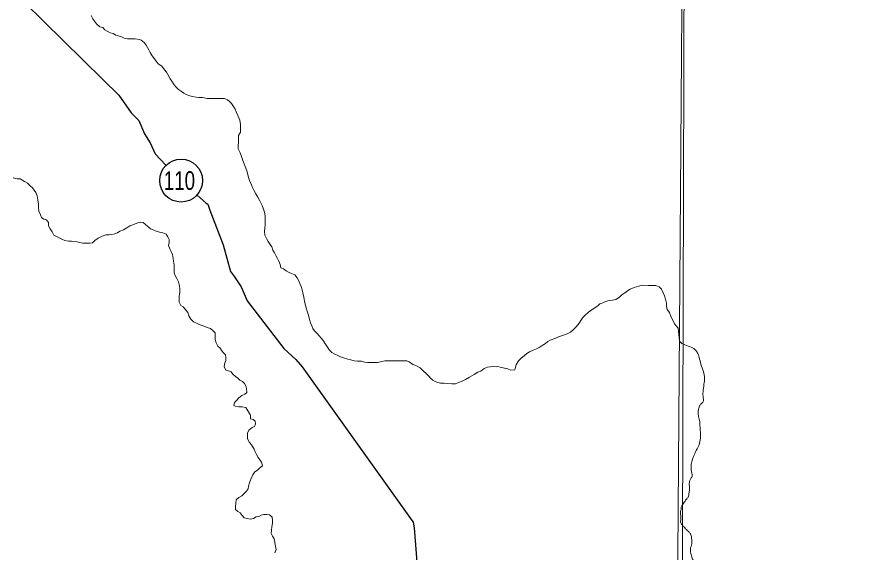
# Model space of a CAD drawing. Extents: x 553962 to 842807, y 8883888 to 9032388.
# Drawn here: x 616016 to 619158, y 8900970 to 8902976 of the extents above; entities that cross this region are included whole.
import ezdxf
from ezdxf.enums import TextEntityAlignment as Align

# ---------------------------------------------------------------- set-up
doc = ezdxf.new("R2010")
doc.units = 0
doc.header["$LTSCALE"] = 20
doc.layers.add('6', color=7, linetype='Continuous', lineweight=13)

msp = doc.modelspace()

# ---------------------------------------------------------------- linework, layer by layer
at = {"layer": '6'}
for points in [[(618662.98, 8924716.12), (618558.35, 8909803.66), (618456.51, 8896026.67)], [(616295.09, 8902981.38), (616301.11, 8902969.11), (616307.15, 8902959.91), (616315.22, 8902949.67), (616327.94, 8902939.08), (616339.54, 8902936.27), (616346.33, 8902927.36), (616366.4, 8902915.64), (616378.11, 8902913.96), (616388.14, 8902907.27)], [(616388.14, 8902907.27), (616406.54, 8902902.24), (616418.25, 8902895.55), (616431.63, 8902893.87), (616441.66, 8902893.87), (616460.06, 8902893.87), (616476.78, 8902890.52), (616482.64, 8902888.49), (616493.77, 8902879.25), (616501.84, 8902870.03), (616510.88, 8902852.65), (616515.89, 8902842.43), (616523.95, 8902830.15), (616532.01, 8902818.89), (616539.07, 8902809.68), (616546.12, 8902800.46), (616560.3, 8902791.21), (616570.38, 8902777.9), (616577.44, 8902768.68), (616582.46, 8902759.48), (616591.5, 8902743.12), (616599.56, 8902730.85), (616605.6, 8902721.64), (616612.66, 8902713.44), (616622.76, 8902703.19), (616633.9, 8902695.99), (616643.02, 8902689.82), (616651.28, 8902684.92), (616664.31, 8902680.51), (616674.47, 8902677.39), (616688.69, 8902675.26), (616698.86, 8902674.18), (616712.08, 8902674.09), (616730.36, 8902669.9), (616742.57, 8902669.82), (616754.77, 8902669.74), (616772.07, 8902669.63), (616784.27, 8902669.55), (616794.45, 8902669.49), (616805.61, 8902665.34), (616813.69, 8902658.16), (616820.77, 8902650.98), (616828.83, 8902639.72), (616834.86, 8902629.5), (616838.87, 8902620.3), (616844.87, 8902606), (616851.87, 8902588.64), (616854.81, 8902572.32), (616854.69, 8902555), (616854.62, 8902543.79), (616847.41, 8902531.61), (616847.33, 8902519.39), (616847.25, 8902508.18), (616846.13, 8902492.91), (616846.05, 8902481.7), (616853.07, 8902466.38), (616858.05, 8902452.08), (616863.04, 8902437.79), (616868.04, 8902425.53), (616872.04, 8902415.32), (616879.05, 8902398.97), (616882.01, 8902385.71), (616884.99, 8902374.48), (616887.96, 8902363.26), (616895.98, 8902345.89)], [(616003.39, 8902372.85), (616017.6, 8902368.68), (616029.8, 8902368.61), (616046.02, 8902359.33), (616057.16, 8902352.13), (616066.25, 8902342.9), (616075.35, 8902334.69), (616081.39, 8902326.51), (616088.45, 8902317.29), (616092.44, 8902305.04), (616095.38, 8902289.74), (616097.31, 8902274.45), (616098.23, 8902260.18), (616099.16, 8902247.95), (616105.18, 8902234.66), (616109.17, 8902224.45), (616118.29, 8902218.28), (616128.44, 8902215.16), (616135.5, 8902205.94), (616135.4, 8902192.7), (616141.43, 8902181.46), (616149.49, 8902170.2), (616155.51, 8902157.93), (616184.9, 8902142.46), (616196.06, 8902138.32), (616210.28, 8902135.17), (616221.47, 8902135.1), (616237.74, 8902133.97), (616250.94, 8902130.83), (616264.15, 8902127.69), (616274.32, 8902127.63), (616289.58, 8902127.53), (616300.78, 8902129.49), (616308.97, 8902137.59), (616321.24, 8902146.68), (616336.56, 8902154.73), (616349.81, 8902158.72), (616363.04, 8902159.66), (616373.22, 8902160.61), (616383.4, 8902162.58), (616393.6, 8902166.59), (616402.8, 8902172.65), (616416.06, 8902177.66), (616429.34, 8902185.72), (616439.56, 8902192.79), (616450.78, 8902196.79), (616459.96, 8902200.81), (616470.15, 8902203.8), (616480.34, 8902206.79), (616490.51, 8902205.7), (616498.59, 8902197.5), (616507.7, 8902190.31), (616517.81, 8902182.1), (616526.94, 8902177.96), (616539.11, 8902172.79), (616551.3, 8902169.66), (616563.48, 8902166.52), (616575.65, 8902161.35), (616582.71, 8902152.14), (616587.73, 8902141.92), (616587.65, 8902130.71), (616584.51, 8902118.51), (616590.53, 8902106.24), (616595.55, 8902097.04)], [(616895.98, 8902345.89), (616899.98, 8902336.69), (616905, 8902326.47), (616912.02, 8902312.16), (616920.08, 8902299.89), (616927.11, 8902286.6), (616936.14, 8902269.22), (616941.13, 8902254.93), (616944.1, 8902243.7), (616947.06, 8902230.44), (616946.98, 8902218.21), (616946.9, 8902207.01), (616946.83, 8902196.82), (616945.73, 8902184.6), (616944.63, 8902172.38), (616945.55, 8902158.11), (616951.56, 8902144.83), (616958.61, 8902134.6), (616965.65, 8902122.33), (616971.69, 8902114.14), (616975.68, 8902101.89), (616982.73, 8902091.66), (616988.75, 8902079.39), (616993.77, 8902070.19), (616997.78, 8902061), (617002.77, 8902047.72), (617005.74, 8902035.48), (617015.88, 8902031.34), (617026.01, 8902024.14), (617037.15, 8902017.96), (617046.28, 8902013.82), (617058.45, 8902008.65), (617066.52, 8901998.41), (617071.54, 8901989.21), (617076.54, 8901976.95), (617081.55, 8901965.71), (617085.53, 8901952.44)], [(616595.55, 8902097.04), (616600.56, 8902085.8), (616602.49, 8902070.51), (616603.44, 8902060.31), (616606.39, 8902046.03), (616606.32, 8902035.85), (616606.19, 8902016.49), (616610.2, 8902007.3), (616616.22, 8901995.03), (616622.23, 8901982.77), (616625.22, 8901972.56), (616627.15, 8901958.29), (616627.05, 8901943), (616624.91, 8901928.76), (616624.84, 8901917.55), (616624.76, 8901906.34), (616630.78, 8901894.08), (616639.9, 8901888.93), (616646.96, 8901880.73), (616657.05, 8901868.44), (616661.03, 8901855.17), (616669.08, 8901842.9), (616678.17, 8901833.67)], [(617085.53, 8901952.44), (617088.51, 8901941.22), (617092.47, 8901925.91), (617094.4, 8901910.62), (617097.37, 8901899.39), (617101.35, 8901886.12), (617104.31, 8901872.86), (617109.29, 8901857.55), (617113.25, 8901841.22), (617117.23, 8901828.97), (617122.24, 8901817.73), (617125.22, 8901807.52), (617132.29, 8901799.33), (617141.37, 8901789.08), (617150.46, 8901778.84), (617157.53, 8901771.66), (617164.59, 8901763.46), (617173.65, 8901749.14), (617180.69, 8901737.89), (617187.74, 8901726.64), (617196.83, 8901718.43), (617207.98, 8901712.25), (617219.14, 8901707.08), (617229.27, 8901701.92), (617240.43, 8901697.78), (617256.68, 8901693.6), (617267.85, 8901690.47), (617281.04, 8901686.31), (617293.25, 8901686.23), (617308.51, 8901686.13), (617319.67, 8901681.99), (617330.85, 8901680.9), (617345.09, 8901680.8), (617355.26, 8901680.74), (617367.47, 8901680.66), (617383.77, 8901684.63), (617395.99, 8901686.59), (617407.19, 8901687.54), (617422.45, 8901687.44), (617437.71, 8901687.34), (617453.98, 8901687.24), (617464.15, 8901687.17), (617477.38, 8901687.09), (617486.5, 8901682.95), (617500.68, 8901673.69), (617511.84, 8901669.55), (617528.05, 8901660.27), (617540.18, 8901647.97), (617550.29, 8901639.76), (617560.39, 8901629.5), (617567.45, 8901620.29), (617575.55, 8901614.12), (617584.67, 8901609.99), (617593.8, 8901605.86), (617603.95, 8901602.74), (617618.19, 8901602.64), (617630.39, 8901601.55), (617646.66, 8901600.42), (617659.89, 8901601.36), (617671.11, 8901605.36), (617685.38, 8901610.36), (617697.63, 8901616.4), (617712.95, 8901625.47), (617730.31, 8901635.55), (617743.6, 8901644.63)], [(617882.82, 8901653.44), (617884.23, 8901658.24), (617887.37, 8901671.47), (617896.63, 8901686.69), (617905.85, 8901696.82), (617918.12, 8901705.91), (617927.33, 8901714), (617937.55, 8901720.04), (617951.84, 8901727.08), (617964.08, 8901732.1), (617973.27, 8901737.13), (617985.53, 8901744.19), (617997.79, 8901752.26), (618005.97, 8901759.34), (618015.16, 8901764.37), (618035.56, 8901771.37), (618045.76, 8901776.4), (618061.06, 8901781.4), (618072.27, 8901785.4), (618081.46, 8901789.42), (618091.66, 8901794.44), (618100.88, 8901803.55), (618112.15, 8901814.69), (618123.43, 8901827.86), (618129.6, 8901838.01), (618137.82, 8901849.16), (618144.99, 8901857.27), (618158.3, 8901869.41), (618171.58, 8901877.47), (618183.85, 8901886.56), (618193.05, 8901893.63), (618201.24, 8901900.71), (618212.46, 8901904.72), (618222.66, 8901908.73), (618235.91, 8901912.72), (618248.12, 8901913.66), (618261.36, 8901916.63), (618274.65, 8901925.71), (618283.86, 8901933.8), (618294.09, 8901941.89), (618304.31, 8901948.95), (618314.53, 8901956.02), (618329.83, 8901962.03), (618347.16, 8901967.02), (618359.39, 8901969.99), (618382.78, 8901969.84), (618396.01, 8901969.76), (618411.26, 8901968.64), (618423.43, 8901964.49), (618431.51, 8901955.27), (618438.54, 8901941.98), (618443.55, 8901930.74), (618447.53, 8901918.49), (618450.48, 8901903.19), (618450.4, 8901891.98), (618453.37, 8901879.74), (618461.43, 8901868.48), (618468.42, 8901850.1), (618476.46, 8901834.77), (618480.46, 8901825.57), (618487.53, 8901818.39), (618494.59, 8901809.18), (618499, 8901761.6)], [(616678.17, 8901833.67), (616690.34, 8901827.48), (616700.48, 8901823.34), (616710.63, 8901819.2), (616720.78, 8901816.08), (616729.9, 8901811.94), (616742.08, 8901807.79), (616751.19, 8901800.6), (616760.28, 8901791.37), (616760.2, 8901780.17), (616760.11, 8901766.92), (616763.08, 8901754.68), (616770.11, 8901741.39), (616778.2, 8901734.21), (616784.24, 8901725), (616791.3, 8901716.8), (616798.37, 8901709.63), (616800.34, 8901699.43), (616800.26, 8901688.22), (616796.13, 8901679.08), (616794, 8901665.85), (616800.01, 8901652.56), (616810.17, 8901649.44), (616819.29, 8901645.31), (616826.36, 8901637.11), (616835.45, 8901627.89), (616844.56, 8901621.71), (616852.65, 8901614.53), (616862.79, 8901609.37), (616869.86, 8901602.2), (616874.88, 8901592.99), (616876.85, 8901582.79), (616878.78, 8901568.52), (616870.6, 8901562.46), (616859.38, 8901557.44), (616848.13, 8901548.34), (616840.94, 8901539.22), (616832.75, 8901531.12), (616829.62, 8901519.93), (616834.29, 8901516.97)], [(617743.6, 8901644.63), (617754.82, 8901648.63), (617767.09, 8901658.74), (617779.91, 8901663.63), (617790.11, 8901664.41), (617803.45, 8901665.98), (617813.65, 8901664.41), (617818.35, 8901665.2), (617827.77, 8901663.63), (617844.24, 8901658.91), (617856.01, 8901657.34), (617867.78, 8901651.85), (617882.82, 8901653.44)], [(616834.29, 8901516.97), (616847.93, 8901514.73), (616860.71, 8901515), (616874.93, 8901511.85), (616892.03, 8901483.22), (616891.94, 8901469.97), (616902.09, 8901466.85), (616910.18, 8901460.69), (616911.13, 8901450.49), (616907, 8901441.35), (616897.82, 8901437.34), (616886.56, 8901427.22), (616881.39, 8901416.05), (616881.32, 8901405.86), (616881.25, 8901394.65), (616888.28, 8901381.36), (616896.35, 8901372.14), (616905.39, 8901355.78), (616909.39, 8901345.57), (616914.41, 8901335.35), (616921.45, 8901324.1), (616927.5, 8901315.91), (616933.54, 8901306.7), (616937.52, 8901293.43), (616926.26, 8901284.34), (616918.08, 8901277.26), (616908.88, 8901271.2), (616900.67, 8901260.05), (616893.43, 8901243.8), (616888.25, 8901229.57), (616885.11, 8901217.36), (616884.03, 8901207.18), (616875.82, 8901197.05), (616867.62, 8901187.93), (616859.43, 8901180.85), (616848.2, 8901174.81), (616838.98, 8901165.7), (616836.87, 8901153.49), (616835.76, 8901140.25), (616835.69, 8901130.06), (616844.79, 8901122.88), (616852.89, 8901116.71), (616860.96, 8901107.49), (616868.02, 8901098.28), (616879.19, 8901096.17), (616891.38, 8901093.03), (616903.61, 8901096.01), (616912.8, 8901102.06), (616922.98, 8901103.02), (616932.18, 8901109.07), (616942.37, 8901111.04), (616953.55, 8901110.97), (616963.72, 8901109.89), (616972.82, 8901101.68), (616974.78, 8901090.46), (616974.69, 8901078.23), (616971.55, 8901065.01), (616970.44, 8901051.77), (616969.34, 8901039.56), (616974.36, 8901029.34), (616980.4, 8901020.13), (616983.36, 8901007.88), (616985.28, 8900990.55), (616988.26, 8900980.35), (616983.08, 8900967.13)]]:
    msp.add_lwpolyline(points, dxfattribs=at)
msp.add_lwpolyline([(618535.25, 8909853.32), (607574.31, 8909890.72), (607543.3, 8898835.28), (618504.23, 8898795.81)], close=True, dxfattribs=at)
at = {"layer": '6', "lineweight": 25}
for points in [[(616044.3, 8903031.21), (616338.7, 8902741.32), (616398.6, 8902682.12), (616445.22, 8902616.83), (616473.64, 8902587.23), (616494.86, 8902537.27), (616516.13, 8902503.61), (616535.34, 8902462.82), (616575.33, 8902420.06)], [(616692.64, 8902307.3), (616726.2, 8902278.07), (616732.3, 8902273.98), (616740.37, 8902251.55), (616789.82, 8902122.07), (616816.96, 8902022.18), (616832.17, 8902001.77)], [(616832.17, 8902001.77), (616857.5, 8901964.03), (616879.73, 8901912.03), (616954.76, 8901814.08), (617016.62, 8901733.48), (617062.31, 8901691.63), (617085.64, 8901664.08), (617491.1, 8901095.85), (617501.24, 8901082.58), (617505.24, 8901061.18), (617519.81, 8900868.6), (617561.01, 8900712.64), (617579.96, 8900602.57), (617583.86, 8900553.66), (617583.69, 8900508.84), (617579.53, 8900483.37), (617569.1, 8900420.23), (617561.63, 8900327.53), (617544.49, 8899823.24), (617553.61, 8899807.94), (617563.76, 8899799.77), (617570.96, 8899793.85)]]:
    msp.add_lwpolyline(points, dxfattribs=at)
msp.add_circle((616632.16, 8902362.25), 80.26, dxfattribs=at)
at = {"layer": '6'}
for points in [[(618499, 8901761.6), (618503.21, 8901756.53), (618514.34, 8901749.34), (618537.29, 8901740.07), (618557.46, 8901729.86), (618566.04, 8901718.5), (618573.23, 8901699.96), (618579.95, 8901674.22), (618589.46, 8901646.4), (618593.28, 8901621.82), (618591.19, 8901598.87), (618587.72, 8901571.05), (618588.41, 8901548.79), (618589.11, 8901536.97), (618583.54, 8901528.62), (618575.89, 8901520.27), (618571.02, 8901504.97), (618569.48, 8901492.94), (618571.13, 8901478.9), (618575.26, 8901458.05), (618576.29, 8901438.23), (618578.35, 8901414.28), (618577.94, 8901397.71), (618572.57, 8901372.72), (618558.53, 8901342.98), (618550.28, 8901324.18), (618544.08, 8901303.32), (618542.64, 8901289.42), (618545.94, 8901266.49), (618547.18, 8901256.17), (618542.02, 8901245.63), (618537.27, 8901235.31), (618536.44, 8901218.16), (618537.06, 8901203.91), (618535, 8901190.08), (618531.9, 8901176.44), (618524.88, 8901167.35), (618516, 8901155.17), (618510.63, 8901147.11), (618506.09, 8901139.06), (618505.27, 8901129.76), (618503, 8901122.95), (618503.41, 8901111.38), (618504.65, 8901093.62), (618504.23, 8901079.99), (618511.46, 8901070.28), (618519.3, 8901060.99), (618531.9, 8901048.18), (618539.33, 8901039.71), (618544.9, 8901022.55), (618545.93, 8901009.74), (618545.52, 8901001.07), (618542.01, 8900989.91), (618540.77, 8900979.79), (618540.36, 8900969.67)], [(618540.36, 8900969.67), (618543.66, 8900960.59), (618545.72, 8900950.88), (618551.71, 8900935.8), (618555.63, 8900926.71), (618563.48, 8900915.77), (618569.88, 8900906.89), (618573.18, 8900897.18), (618577.92, 8900883.32), (618586.59, 8900870.72), (618610.75, 8900847.38), (618615.08, 8900841.39), (618621.07, 8900831.27), (618629.74, 8900821.36), (618642.95, 8900802.15), (618653.89, 8900791.61), (618661.94, 8900779.63), (618670.82, 8900769.31), (618679.7, 8900755.26), (618692.49, 8900737.79), (618702.4, 8900722.92), (618709.42, 8900710.73), (618718.3, 8900699.37), (618732.02, 8900673.76), (618745.65, 8900641.54), (618759.89, 8900608.7), (618767.2, 8900587.44), (618772.21, 8900563.6), (618773.47, 8900548.55), (618775.73, 8900531.99), (618774.97, 8900518.69), (618772.97, 8900503.39), (618773.47, 8900489.59), (618773.72, 8900477.8), (618776.22, 8900454.69), (618779.98, 8900412.26), (618783.5, 8900370.09), (618785.25, 8900355.28), (618793.03, 8900343.73), (618799.05, 8900336.71), (618806.33, 8900333.44), (618816.61, 8900332.94), (618828.91, 8900328.92), (618840.45, 8900325.91), (618847.98, 8900320.89), (618861.02, 8900313.11), (618873.82, 8900306.33), (618910.31, 8900287.73), (618933.14, 8900275.68), (618944.94, 8900266.14), (618958.74, 8900247.31), (618965.51, 8900231.75), (618972.54, 8900214.93), (618978.81, 8900198.36), (618987.59, 8900189.83)]]:
    msp.add_spline(points, degree=3, dxfattribs=at)
at = {"layer": '6', "lineweight": 40}
msp.add_spline([(616186.66, 8898760.17), (616684.43, 8899006.26), (616785.11, 8899051), (616869, 8899062.19), (616986.45, 8899062.19), (617081.53, 8899090.15), (617148.65, 8899157.27), (617221.35, 8899297.09), (617254.91, 8899358.61), (617305.25, 8899392.17), (617389.14, 8899526.4), (617528.97, 8899738.93), (617601.67, 8899834.01), (617685.57, 8899990.62), (617752.68, 8900091.29), (617853.36, 8900164), (618004.37, 8900197.55), (618194.53, 8900231.11), (618356.72, 8900225.52), (618479.77, 8900219.93), (618614, 8900152.81), (618703.48, 8900119.25), (618748.23, 8900113.66), (618832.12, 8900175.18), (618910.42, 8900231.11), (618977.54, 8900225.52), (619067.02, 8900203.15), (619100.58, 8900214.33), (619117.36, 8900253.48), (619106.17, 8900320.6), (619117.36, 8900421.27), (619106.17, 8900516.35), (619078.21, 8900566.69), (619094.99, 8900611.43), (619145.32, 8900723.29), (619229.22, 8900868.71), (619307.52, 8900958.19), (619380.23, 8901019.72), (619512.75, 8901031.23), (619643.1, 8901014.12), (619824.84, 8900993.83)], degree=3, dxfattribs=at)

# ---------------------------------------------------------------- texts
at = {"layer": '6', "width": 0.75}
msp.add_text('110', height=70, dxfattribs=at).set_placement((616625.83, 8902327.58), align=Align.CENTER)

doc.saveas('drawing.dxf')
